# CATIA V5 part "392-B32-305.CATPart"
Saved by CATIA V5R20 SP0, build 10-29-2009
Part number: 392-B32-305
Definition: NONE
Nomenclature: 392-B32-305
Source: Unknown
Description: 392-B32-305
Bounding box of the stored display mesh (mm): x 0 to 305, y -15.618 to 15.618, z -15.5 to 15.5
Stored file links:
  C:\Users\Utente\Desktop\IO LAVORO\3D X SITO CF\X SITO\3D files 392B\392-B32-305.CATPart
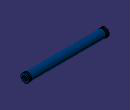
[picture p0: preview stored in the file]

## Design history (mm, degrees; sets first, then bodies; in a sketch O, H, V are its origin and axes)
Body1 "392-B32-305" (main body)
  Solid1: solid without history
